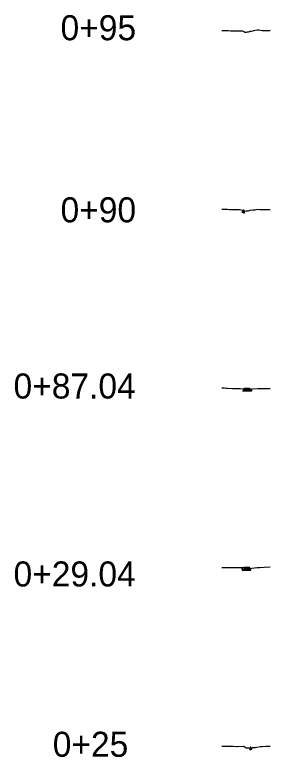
# Model space of a CAD drawing. Extents: x -577 to 1138, y -35 to 4556.
# Drawn here: x -577 to 135, y 2482 to 4556 of the extents above; entities that cross this region are included whole.
import ezdxf

# ---------------------------------------------------------------- set-up
doc = ezdxf.new("R2010")
doc.units = 0
for name, color, linetype in [('MD_P_Surface_Non-Reinforced_Concrete_Pavement', 7, 'Continuous'), ('SC_Scratch1', 7, 'Continuous'), ('XS_X_Ground_Line', 7, 'Continuous')]:
    doc.layers.add(name, color=color, linetype=linetype)

msp = doc.modelspace()

# ---------------------------------------------------------------- linework, layer by layer
at = {"layer": 'MD_P_Surface_Non-Reinforced_Concrete_Pavement'}
for p, q in [((56.8, 4004.3), (56.8, 4005.5)), ((56.8, 4005.5), (58.1, 4005.5)), ((56.8, 4004), (56.8, 4004.3)), ((58.1, 4004), (56.8, 4004)), ((58.1, 4005.5), (58.6, 4005.5)), ((58.9, 4004), (58.1, 4004)), ((58.6, 4005.5), (59.8, 4005.5)), ((59.8, 4004), (58.9, 4004)), ((59.5, 4010.6), (60.7, 4010.8)), ((59.5, 4005.5), (59.5, 4010.6)), ((60.7, 4005.5), (59.5, 4005.5)), ((59.8, 4005.5), (60.9, 4005.5)), ((60.9, 4004), (59.8, 4004)), ((60.7, 4010.8), (60.7, 4005.5)), ((60.9, 4005.5), (61.4, 4005.5)), ((60.9, 4003.2), (60.9, 4004)), ((60.9, 4001.5), (60.9, 4003.2)), ((61.4, 4005.5), (62.8, 4005.5)), ((62.8, 4005.5), (62.8, 4004.9)), ((62.8, 4004.9), (62.8, 4001.5)), ((61.4, 4001.5), (60.9, 4001.5)), ((62.1, 4001.5), (61.4, 4001.5)), ((62.8, 4001.5), (62.1, 4001.5)), ((59.1, 3505.4), (59.1, 3505.5)), ((59.1, 3505.5), (59.2, 3505.5)), ((59.2, 3505.5), (60.5, 3505.5)), ((60.5, 3505.5), (60.8, 3505.5)), ((60.8, 3505.5), (61.1, 3505.5)), ((61.1, 3505.5), (61.6, 3505.5)), ((61.6, 3505.5), (63.8, 3505.5)), ((61.7, 3511.7), (63, 3512)), ((61.7, 3505.5), (61.7, 3511.7)), ((63, 3505.5), (61.7, 3505.5)), ((63, 3512), (63, 3505.5)), ((63, 3512), (77, 3512)), ((76, 3511.5), (63, 3511.5)), ((63.8, 3505.5), (63.8, 3505.5)), ((63.8, 3505.5), (64.2, 3505.5)), ((64, 3510.5), (64, 3506.5)), ((64, 3510.5), (76, 3510.5)), ((70, 3506.5), (64, 3506.5)), ((64, 3505.5), (76, 3505.5)), ((64.2, 3505.5), (64.3, 3505.5)), ((64.3, 3505.5), (64.7, 3505.5)), ((64.7, 3505.5), (65.3, 3505.5)), ((65.3, 3505.5), (66, 3505.5)), ((66, 3505.5), (66.3, 3505.5)), ((66.3, 3505.5), (66.7, 3505.5)), ((66.7, 3505.5), (67.3, 3505.5)), ((67.3, 3505.5), (68, 3505.5)), ((68, 3505.5), (68.3, 3505.5)), ((68.3, 3505.5), (69, 3505.5)), ((69, 3505.5), (69.3, 3505.5)), ((69.3, 3505.5), (69.7, 3505.5)), ((69.7, 3505.5), (70.3, 3505.5)), ((76, 3506.5), (70, 3506.5)), ((70.3, 3505.5), (71, 3505.5)), ((71, 3505.5), (71.3, 3505.5)), ((71.3, 3505.5), (71.7, 3505.5)), ((71.7, 3505.5), (72.3, 3505.5)), ((72.3, 3505.5), (73, 3505.5)), ((77, 3511.5), (72.4, 3511.5)), ((73, 3505.5), (73.3, 3505.5)), ((73.3, 3505.5), (74, 3505.5)), ((74, 3505.5), (74.3, 3505.5)), ((74.3, 3505.5), (74.7, 3505.5)), ((74.7, 3505.5), (75.3, 3505.5)), ((75.3, 3505.5), (76, 3505.5)), ((77, 3511.5), (76, 3511.5)), ((76, 3510.5), (76, 3506.5)), ((76, 3505.5), (77, 3505.5)), ((76, 3505.5), (76.3, 3505.5)), ((76.3, 3505.5), (76.7, 3505.5)), ((76.7, 3505.5), (77.3, 3505.5)), ((77, 3505.5), (77, 3512)), ((77, 3512), (83.3, 3510.2)), ((77, 3512), (77, 3511.5)), ((77, 3505.5), (77, 3511.5)), ((83.3, 3505.5), (77, 3505.5)), ((77.3, 3505.5), (78, 3505.5)), ((78, 3505.5), (78.3, 3505.5)), ((78.3, 3505.5), (79, 3505.5)), ((79, 3505.5), (79.3, 3505.5)), ((79.3, 3505.5), (79.7, 3505.5)), ((79.7, 3505.5), (80.3, 3505.5)), ((80.3, 3505.5), (81, 3505.5)), ((81, 3505.5), (81.3, 3505.5)), ((81.3, 3505.5), (81.7, 3505.5)), ((81.7, 3505.5), (82.3, 3505.5)), ((82.3, 3505.5), (83, 3505.5)), ((83, 3505.5), (83.3, 3505.5)), ((83.3, 3510.2), (83.3, 3505.5)), ((83.3, 3505.5), (83.3, 3504)), ((59.1, 3504), (59.1, 3505.4)), ((59.2, 3504), (59.1, 3504)), ((59.3, 3504), (59.2, 3504)), ((59.2, 3504), (59.2, 3504)), ((60.8, 3504), (59.3, 3504)), ((61.3, 3504), (60.8, 3504)), ((61.6, 3504), (61.3, 3504)), ((62.9, 3504), (61.6, 3504)), ((63.8, 3504), (62.9, 3504)), ((64.3, 3504), (63.8, 3504)), ((64.4, 3504), (64.3, 3504)), ((64.3, 3504), (64.3, 3504)), ((65.3, 3504), (64.4, 3504)), ((66.3, 3504), (65.3, 3504)), ((66.4, 3504), (66.3, 3504)), ((66.3, 3504), (66.3, 3504)), ((67.3, 3504), (66.4, 3504)), ((68.3, 3504), (67.3, 3504)), ((69.3, 3504), (68.3, 3504)), ((68.3, 3504), (68.3, 3504)), ((69.4, 3504), (69.3, 3504)), ((69.3, 3504), (69.3, 3504)), ((70.3, 3504), (69.4, 3504)), ((71.3, 3504), (70.3, 3504)), ((71.4, 3504), (71.3, 3504)), ((71.3, 3504), (71.3, 3504)), ((72.3, 3504), (71.4, 3504)), ((73.3, 3504), (72.3, 3504)), ((74.3, 3504), (73.3, 3504)), ((73.3, 3504), (73.3, 3504)), ((74.4, 3504), (74.3, 3504)), ((74.3, 3504), (74.3, 3504)), ((75.3, 3504), (74.4, 3504)), ((76.3, 3504), (75.3, 3504)), ((76.4, 3504), (76.3, 3504)), ((76.3, 3504), (76.3, 3504)), ((77.3, 3504), (76.4, 3504)), ((78.3, 3504), (77.3, 3504)), ((79.3, 3504), (78.3, 3504)), ((78.3, 3504), (78.3, 3504)), ((79.4, 3504), (79.3, 3504)), ((79.3, 3504), (79.3, 3504)), ((80.3, 3504), (79.4, 3504)), ((81.3, 3504), (80.3, 3504)), ((81.4, 3504), (81.3, 3504)), ((81.3, 3504), (81.3, 3504)), ((82.3, 3504), (81.4, 3504)), ((83.3, 3504), (82.3, 3504)), ((83.3, 3504), (83.3, 3504)), ((83.3, 3504), (83.3, 3504)), ((56.7, 3009.7), (63, 3012.2)), ((56.7, 3005.7), (56.7, 3009.7)), ((63, 3012.2), (77, 3012.2)), ((63, 3012.2), (63, 3005.7)), ((64, 3011.7), (63, 3011.7)), ((77, 3011.7), (64, 3011.7)), ((64, 3006.7), (64, 3010.7)), ((64, 3010.7), (76, 3010.7)), ((76, 3010.7), (76, 3006.7)), ((78.3, 3011.7), (77, 3012.2)), ((77, 3005.7), (77, 3012.2)), ((77, 3011.7), (77, 3005.7)), ((78.3, 3005.7), (78.3, 3011.7)), ((57, 3005.7), (56.7, 3005.7)), ((56.7, 3005.7), (56.7, 3004.3)), ((56.7, 3004.3), (56.7, 3004.2)), ((56.7, 3004.2), (57.6, 3004.2)), ((57.7, 3005.7), (57, 3005.7)), ((57.6, 3004.2), (57.7, 3004.2)), ((58, 3005.7), (57.7, 3005.7)), ((57.7, 3004.2), (57.7, 3004.2)), ((57.7, 3004.2), (58.7, 3004.2)), ((58.7, 3005.7), (58, 3005.7)), ((59, 3005.7), (58.7, 3005.7)), ((58.7, 3004.2), (59.6, 3004.2)), ((59.7, 3005.7), (59, 3005.7)), ((59.6, 3004.2), (59.7, 3004.2)), ((60, 3005.7), (59.7, 3005.7)), ((59.7, 3004.2), (59.7, 3004.2)), ((59.7, 3004.2), (60.7, 3004.2)), ((60.7, 3005.7), (60, 3005.7)), ((61.3, 3005.7), (60.7, 3005.7)), ((60.7, 3004.2), (61.6, 3004.2)), ((61.7, 3005.7), (61.3, 3005.7)), ((61.6, 3004.2), (61.7, 3004.2)), ((62.3, 3005.7), (61.7, 3005.7)), ((61.7, 3004.2), (61.7, 3004.2)), ((61.7, 3004.2), (62.7, 3004.2)), ((62.7, 3005.7), (62.3, 3005.7)), ((63, 3005.7), (62.7, 3005.7)), ((62.7, 3004.2), (62.7, 3004.2)), ((62.7, 3004.2), (63.7, 3004.2)), ((63, 3005.7), (64, 3005.7)), ((63.7, 3005.7), (63, 3005.7)), ((64, 3005.7), (63.7, 3005.7)), ((63.7, 3004.2), (64.6, 3004.2)), ((70, 3006.7), (64, 3006.7)), ((64, 3005.7), (76, 3005.7)), ((64.7, 3005.7), (64, 3005.7)), ((64.6, 3004.2), (64.7, 3004.2)), ((65, 3005.7), (64.7, 3005.7)), ((64.7, 3004.2), (64.7, 3004.2)), ((64.7, 3004.2), (65.7, 3004.2)), ((65.7, 3005.7), (65, 3005.7)), ((66, 3005.7), (65.7, 3005.7)), ((65.7, 3004.2), (66.6, 3004.2)), ((66.7, 3005.7), (66, 3005.7)), ((66.6, 3004.2), (66.7, 3004.2)), ((67.3, 3005.7), (66.7, 3005.7)), ((66.7, 3004.2), (67.6, 3004.2)), ((67.7, 3005.7), (67.3, 3005.7)), ((67.6, 3004.2), (67.7, 3004.2)), ((68, 3005.7), (67.7, 3005.7)), ((67.7, 3004.2), (67.7, 3004.2)), ((67.7, 3004.2), (68.7, 3004.2)), ((68.7, 3005.7), (68, 3005.7)), ((69.3, 3005.7), (68.7, 3005.7)), ((68.7, 3004.2), (69.6, 3004.2)), ((69.7, 3005.7), (69.3, 3005.7)), ((69.6, 3004.2), (69.7, 3004.2)), ((70, 3005.7), (69.7, 3005.7)), ((69.7, 3004.2), (69.7, 3004.2)), ((69.7, 3004.2), (70.7, 3004.2)), ((76, 3006.7), (70, 3006.7)), ((70.7, 3005.7), (70, 3005.7)), ((71, 3005.7), (70.7, 3005.7)), ((70.7, 3004.2), (70.7, 3004.2)), ((70.7, 3004.2), (71.7, 3004.2)), ((71.7, 3005.7), (71, 3005.7)), ((72, 3005.7), (71.7, 3005.7)), ((71.7, 3004.2), (71.7, 3004.2)), ((71.7, 3004.2), (72.7, 3004.2)), ((72.7, 3005.7), (72, 3005.7)), ((73, 3005.7), (72.7, 3005.7)), ((72.7, 3004.2), (72.7, 3004.2)), ((72.7, 3004.2), (73.7, 3004.2)), ((73.7, 3005.7), (73, 3005.7)), ((74, 3005.7), (73.7, 3005.7)), ((73.7, 3004.2), (74.6, 3004.2)), ((74.7, 3005.7), (74, 3005.7)), ((74.6, 3004.2), (74.7, 3004.2)), ((75.3, 3005.7), (74.7, 3005.7)), ((74.7, 3004.2), (75.6, 3004.2)), ((75.7, 3005.7), (75.3, 3005.7)), ((75.6, 3004.2), (75.7, 3004.2)), ((76, 3005.7), (75.7, 3005.7)), ((75.7, 3004.2), (77, 3004.2)), ((76, 3005.7), (77, 3005.7)), ((78.4, 3005.7), (76, 3005.7)), ((77, 3005.7), (78.3, 3005.7)), ((77, 3004.2), (78.4, 3004.2)), ((78.7, 3005.7), (78.4, 3005.7)), ((78.4, 3004.2), (78.8, 3004.2)), ((79.2, 3005.7), (78.7, 3005.7)), ((78.8, 3004.2), (79.2, 3004.2)), ((80.8, 3005.7), (79.2, 3005.7)), ((79.2, 3004.2), (80.7, 3004.2)), ((80.7, 3004.2), (80.8, 3004.2)), ((80.9, 3005.7), (80.8, 3005.7)), ((80.8, 3005.7), (80.8, 3005.7)), ((80.8, 3004.2), (80.9, 3004.2)), ((80.9, 3005.6), (80.9, 3005.7)), ((80.9, 3004.2), (80.9, 3005.6)), ((81.4, 2510.4), (80.1, 2510.7)), ((80.1, 2510.7), (80.1, 2505.7)), ((81.4, 2505.7), (81.4, 2510.4)), ((78, 2505.7), (78, 2503.7)), ((78.8, 2505.7), (78, 2505.7)), ((78, 2503.7), (78, 2501.7)), ((78, 2501.7), (78.4, 2501.7)), ((78.4, 2501.7), (78.8, 2501.7)), ((79.1, 2505.7), (78.8, 2505.7)), ((78.8, 2501.7), (79.9, 2501.7)), ((80.5, 2505.7), (79.1, 2505.7)), ((79.9, 2502.6), (79.9, 2504.2)), ((79.9, 2504.2), (80.5, 2504.2)), ((79.9, 2501.7), (79.9, 2502.6)), ((80.1, 2505.7), (81.4, 2505.7)), ((81.2, 2505.7), (80.5, 2505.7)), ((80.5, 2504.2), (81.5, 2504.2)), ((82.1, 2505.7), (81.2, 2505.7)), ((81.5, 2504.2), (82.1, 2504.2)), ((83.7, 2505.7), (82.1, 2505.7)), ((82.1, 2504.2), (83.6, 2504.2)), ((83.6, 2504.2), (83.7, 2504.2)), ((84, 2505.7), (83.7, 2505.7)), ((83.7, 2505.7), (83.7, 2505.7)), ((83.7, 2504.2), (84, 2504.2)), ((84, 2505.5), (84, 2505.7)), ((84, 2504.2), (84, 2505.5))]:
    msp.add_line(p, q, dxfattribs=at)
at = {"layer": 'XS_X_Ground_Line'}
for p, q in [((0, 4512.5), (3.1, 4512.3)), ((3.1, 4512.3), (14.8, 4511.7)), ((14.8, 4511.7), (18, 4511.7)), ((18, 4511.7), (18, 4511.7)), ((18, 4511.7), (18.1, 4511.7)), ((18.1, 4511.7), (18.2, 4511.7)), ((18.2, 4511.7), (25.6, 4511.6)), ((25.6, 4511.6), (25.8, 4511.6)), ((25.8, 4511.6), (26.5, 4511.6)), ((26.5, 4511.6), (27.1, 4511.6)), ((27.1, 4511.6), (27.1, 4511.6)), ((27.1, 4511.6), (27.2, 4511.6)), ((27.2, 4511.6), (28.7, 4511.5)), ((28.7, 4511.5), (29.2, 4511.5)), ((29.2, 4511.5), (29.4, 4511.5)), ((29.4, 4511.5), (29.6, 4511.5)), ((29.6, 4511.5), (29.7, 4511.5)), ((29.7, 4511.5), (50.9, 4511.5)), ((50.9, 4511.5), (58, 4510.7)), ((58, 4510.7), (61.4, 4510.3)), ((61.4, 4510.3), (62, 4509.1)), ((62, 4509.1), (63.3, 4507.3)), ((63.3, 4507.3), (65.6, 4507.5)), ((65.6, 4507.5), (68.8, 4507.7)), ((68.8, 4507.7), (72.1, 4508.2)), ((72.1, 4508.2), (74.3, 4508.3)), ((74.3, 4508.3), (78.1, 4509.7)), ((78.1, 4509.7), (78.6, 4509.9)), ((78.6, 4509.9), (80.1, 4510)), ((80.1, 4510), (82.2, 4510.4)), ((82.2, 4510.4), (87.3, 4511.1)), ((87.3, 4511.1), (88.7, 4511.8)), ((88.7, 4511.8), (98.4, 4513.9)), ((98.4, 4513.9), (103.3, 4513.9)), ((103.3, 4513.9), (108.5, 4512.9)), ((108.5, 4512.9), (113.2, 4511.8)), ((113.2, 4511.8), (114.2, 4511.8)), ((114.2, 4511.8), (119.5, 4511.8)), ((119.5, 4511.8), (124.5, 4511.9)), ((124.5, 4511.9), (124.8, 4511.9)), ((124.8, 4511.9), (132.4, 4512.4)), ((132.4, 4512.4), (132.5, 4512.5)), ((132.5, 4512.5), (133.8, 4512.5)), ((133.8, 4512.5), (134.4, 4512.6)), ((134.4, 4512.6), (134.4, 4512.6)), ((134.4, 4512.6), (135, 4512.5)), ((0, 4013.2), (1.8, 4013.1)), ((1.8, 4013.1), (7.7, 4012.8)), ((7.7, 4012.8), (11.2, 4012.6)), ((11.2, 4012.6), (12.6, 4012.5)), ((12.6, 4012.5), (16.4, 4012.4)), ((16.4, 4012.4), (21.2, 4012.1)), ((21.2, 4012.1), (27, 4011.8)), ((27, 4011.8), (31.1, 4011.6)), ((31.1, 4011.6), (49.9, 4011.6)), ((49.9, 4011.6), (53.8, 4011.2)), ((53.8, 4011.2), (61.7, 4010.2)), ((61.7, 4010.2), (62.8, 4008.1)), ((62.8, 4008.1), (63.2, 4007.5)), ((63.2, 4007.5), (68, 4007.9)), ((63.2, 4007.5), (63.2, 4007.5)), ((68, 4007.9), (68, 4007.9)), ((68, 4007.9), (68, 4007.9)), ((68, 4007.9), (68.1, 4007.9)), ((68.1, 4007.9), (73.9, 4008)), ((73.9, 4008), (74.9, 4008.4)), ((74.9, 4008.4), (79.4, 4010.2)), ((79.4, 4010.2), (86.5, 4010.9)), ((86.5, 4010.9), (92.8, 4011.3)), ((92.8, 4011.3), (100.8, 4012.5)), ((100.8, 4012.5), (106.5, 4011.8)), ((106.5, 4011.8), (112.5, 4011.8)), ((112.5, 4011.8), (120.6, 4011.9)), ((120.6, 4011.9), (126.4, 4012)), ((126.4, 4012), (127.1, 4012.1)), ((127.1, 4012.1), (129.7, 4012)), ((129.7, 4012), (135, 4012.2)), ((0, 3513.8), (0.5, 3513.8)), ((0.5, 3513.8), (2.5, 3513.7)), ((2.5, 3513.7), (6.3, 3513.3)), ((6.3, 3513.3), (13.5, 3512.9)), ((13.5, 3512.9), (14.8, 3512.9)), ((14.8, 3512.9), (15.4, 3512.8)), ((15.4, 3512.8), (16.1, 3512.8)), ((16.1, 3512.8), (29.7, 3512)), ((29.7, 3512), (39.2, 3511.7)), ((39.2, 3511.7), (49.2, 3511.7)), ((49.2, 3511.7), (51.3, 3511.4)), ((51.3, 3511.4), (58, 3510.6)), ((58, 3510.6), (61.2, 3510.4)), ((61.2, 3510.4), (61.7, 3510.3)), ((61.7, 3510.3), (62.3, 3509.8)), ((62.3, 3509.8), (63.7, 3507.6)), ((63.7, 3507.6), (63.8, 3507.3)), ((63.8, 3507.3), (67.6, 3507.7)), ((67.6, 3507.7), (68.6, 3507.8)), ((68.6, 3507.8), (73.5, 3507.9)), ((68.6, 3507.8), (68.6, 3507.8)), ((73.5, 3507.9), (73.9, 3507.9)), ((73.9, 3507.9), (74, 3508)), ((74, 3508), (75, 3508.4)), ((75, 3508.4), (79.9, 3510.3)), ((79.9, 3510.3), (84.3, 3510.8)), ((84.3, 3510.8), (100.8, 3511.7)), ((100.8, 3511.7), (102.3, 3511.9)), ((102.3, 3511.9), (103.3, 3511.8)), ((103.3, 3511.8), (116.3, 3511.9)), ((116.3, 3511.9), (121.3, 3511.9)), ((121.3, 3511.9), (124.9, 3512)), ((124.9, 3512), (126.2, 3512.1)), ((126.2, 3512.1), (131, 3512.1)), ((131, 3512.1), (135, 3512.2)), ((0, 3012), (1.9, 3012)), ((1.9, 3012), (7.8, 3011.9)), ((7.8, 3011.9), (7.8, 3011.9)), ((7.8, 3011.9), (7.9, 3011.9)), ((7.9, 3011.9), (8.2, 3011.9)), ((8.2, 3011.9), (28.1, 3011.8)), ((28.1, 3011.8), (30.5, 3011.8)), ((30.5, 3011.8), (30.8, 3011.8)), ((30.8, 3011.8), (31.2, 3011.8)), ((31.2, 3011.8), (32.2, 3011.8)), ((32.2, 3011.8), (32.5, 3011.8)), ((32.5, 3011.8), (32.6, 3011.8)), ((32.6, 3011.8), (32.8, 3011.8)), ((32.8, 3011.8), (33, 3011.8)), ((33, 3011.8), (37.6, 3011.7)), ((37.6, 3011.7), (43.6, 3011.5)), ((43.6, 3011.5), (47.1, 3011.3)), ((47.1, 3011.3), (58.9, 3011.3)), ((58.9, 3011.3), (60.9, 3011.3)), ((60.9, 3011.3), (68.8, 3008.2)), ((68.8, 3008.2), (69.1, 3008.1)), ((69.1, 3008.1), (69.2, 3008.1)), ((69.2, 3008.1), (69.8, 3008.1)), ((69.8, 3008.1), (70, 3008.1)), ((70, 3008.1), (78, 3007.7)), ((78, 3007.7), (78.6, 3008)), ((78.6, 3008), (79.5, 3008.5)), ((79.5, 3008.5), (83.6, 3009.9)), ((83.6, 3009.9), (91.3, 3010.5)), ((91.3, 3010.5), (98.5, 3011.7)), ((98.5, 3011.7), (101.4, 3011.7)), ((101.4, 3011.7), (102, 3011.8)), ((102, 3011.8), (105.9, 3011.9)), ((105.9, 3011.9), (118.4, 3012.4)), ((118.4, 3012.4), (135, 3013)), ((135, 3013), (135, 3013)), ((0, 2512.2), (0.5, 2512.1)), ((0.5, 2512.1), (0.6, 2512.1)), ((0.6, 2512.1), (6.8, 2512)), ((6.8, 2512), (6.9, 2512)), ((6.9, 2512), (6.9, 2512)), ((6.9, 2512), (7.3, 2511.9)), ((7.3, 2511.9), (17.7, 2511.9)), ((17.7, 2511.9), (24.9, 2511.9)), ((24.9, 2511.9), (25.5, 2511.9)), ((25.5, 2511.9), (26.9, 2511.9)), ((26.9, 2511.9), (29.6, 2511.9)), ((29.6, 2511.9), (30.6, 2511.9)), ((30.6, 2511.9), (30.9, 2511.9)), ((30.9, 2511.9), (31.7, 2511.9)), ((31.7, 2511.9), (32.2, 2511.9)), ((32.2, 2511.9), (42.5, 2511.8)), ((42.5, 2511.8), (42.7, 2511.8)), ((42.7, 2511.8), (43, 2511.8)), ((43, 2511.8), (43.1, 2511.8)), ((43.1, 2511.8), (43.3, 2511.8)), ((43.3, 2511.8), (43.7, 2511.8)), ((43.7, 2511.8), (43.9, 2511.8)), ((43.9, 2511.8), (43.9, 2511.8)), ((43.9, 2511.8), (44.1, 2511.8)), ((44.1, 2511.8), (44.2, 2511.8)), ((44.2, 2511.8), (61.3, 2511.9)), ((61.3, 2511.9), (62.1, 2511.3)), ((62.1, 2511.3), (68.2, 2508.1)), ((97.9, 2509.5), (107.9, 2511.1)), ((107.9, 2511.1), (112.3, 2511.8)), ((112.3, 2511.8), (123.1, 2512.2)), ((123.1, 2512.2), (132.1, 2512.5)), ((132.1, 2512.5), (134.1, 2512.7)), ((134.1, 2512.7), (134.8, 2512.7)), ((134.8, 2512.7), (135, 2512.7)), ((68.2, 2508.1), (72.3, 2507.7)), ((72.3, 2507.7), (76, 2507.5)), ((76, 2507.5), (76.7, 2507.9)), ((76.7, 2507.9), (77.1, 2508.1)), ((77.1, 2508.1), (79.1, 2508.1)), ((79.1, 2508.1), (84.4, 2508.2)), ((84.4, 2508.2), (94.2, 2508.9)), ((94.2, 2508.9), (97.9, 2509.5))]:
    msp.add_line(p, q, dxfattribs=at)

# ---------------------------------------------------------------- texts
at = {"layer": 'SC_Scratch1'}
for s, p in [('0+95', (-449.9, 4484.8)), ('0+90', (-449.9, 3976)), ('0+87.04', (-581.1, 3483.7)), ('0+29.04', (-581.1, 2958.5)), ('0+25', (-471.7, 2482.6))]:
    msp.add_text(s, height=70, dxfattribs=at).set_placement(p)

doc.saveas('drawing.dxf')
